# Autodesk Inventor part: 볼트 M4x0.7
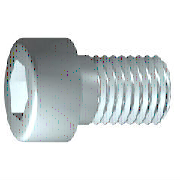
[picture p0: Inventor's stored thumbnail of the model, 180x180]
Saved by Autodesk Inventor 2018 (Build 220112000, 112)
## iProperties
IsCustomPart: 0
Created: 2012-02
Part Number: 볼트 M4x0.7
Material: 스테인리스강
Description: 6각 소켓 머리 캡 나사
Document SubType Name: Modeling
Standard: ISO 4762
Designer: mduedu
Standard Revision: Fourth edition 2004-03-01
Standards Organization: ISO
Language: ko-KR
Size Designation: M4 x 12
Categories: <MemberInstance><Categories><Category DisplayName="조임쇠" InternalName="e4da775c-781d-43d5-af7c-5136215cf5a6" Mnemonic="FSTN"><Category DisplayName="볼트" InternalN
Density: 7.75 g/cm^3
Appearance: 반광택
Author: mduedu
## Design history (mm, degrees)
sketch "스케치1"
  geometry: L1 (-1, 0)-(12, 0); L2 (12, 0)-(12, 2); L3 (12, 2)-(1.75, 2); L4 (1.75, 2)-(1.32, 2); L5 (1.32, 2)-(0, 2); L6 (0, 2)-(0, 3.5); L7 (0, 3.5)-(-4, 3.5); L8 (-4, 3.5)-(-4, 1.732); L9 (-4, 1.732)-(-2, 1.732); L10 (-2, 1.732)-(-1, 0); L11 (-7.2, 0)-(15.2, 0) reference; L12 (0, -0.7)-(0, 4.2) reference; L13 (1.75, 2)-(0, 2)
  constraints: 22 end point, 6 parallel, 2 collinear, 2 perpendicular, 1 horizontal, 1 point on line
  dimensions: "d1" = 10.25 distance from line of L3.end L2 (= GEL); "d2" = 0.42952 distance of L4.end L3.end (computed from GAL); "d3" = 4 distance between parallel lines of L8 L6 (= KOH); "d4" = 2 distance of L8.end L9.end (= INTI); "d5" = 60 deg angle of L10 L1; "d6" = 4 diameter of L3 L1 (= GD); "d7" = 4 diameter of L5 L1 (= BDM); "d8" = 3.4641 diameter of L9 L1 (= 1.1547 x SW); "d9" = 7 diameter of L7 L1 (= KOD); "d26" = 12 distance between parallel lines of L12 L2 (= NLG)
revolve "본체" sketch "스케치1" stored, may be unused: angle "d10" = 90 deg
sketch "스케치2"
  geometry: L1 (0, -4.9)-(0, 4.9) reference; L2 (-4.9, 0)-(4.9, 0) reference; L3 (1.732, 0)-(0.866, -1.5); L4 (0.866, -1.5)-(-0.866, -1.5); L5 (-0.866, -1.5)-(-1.732, 0); L6 (-1.732, 0)-(-0.866, 1.5); L7 (-0.866, 1.5)-(0.866, 1.5); L8 (0.866, 1.5)-(1.732, 0); 2 further points
  constraints: 12 end point, 1 coincident, 1 horizontal alignment, 1 point on line, 12 other
extrude "슬롯" join sketch "스케치2" stored distance "d11" = 10; taper "d12" = 0 deg
workplane "Work Plane1"
fillet "Fillet2" dims "d30" = 0.1 (= R)
body "Solid1"
fillet "모깎기1" dims "d17" = 0.4 (= RR)
feature "스레드" dims "d13" = 10.25 (= GEL), "d14" = 0
chamfer "모따기1" distance "d15" = 0.42941 (= -0.5 x SPD + 0.5 x GD); stored, may be unused: second distance "d16" = 0.42941 (= GUL), angle "d27" = 45 deg
other parameters: "GD" = 4 [user parameter; used in 2 equation terms], "NLG" = 12 [user parameter; used in 1 equation term], "GEL" = 10.25 [user parameter; used in 2 equation terms], "KOD" = 7 [user parameter; used in 1 equation term], "KOH" = 4 [user parameter; used in 1 equation term], "INTI" = 2 [user parameter; used in 1 equation term], "GAL" = 0.42941 (= 0.61345 x PTC) [user parameter; used in 1 equation term], "GUL" = 0.42941 (= 0.61345 x PTC) [user parameter; used in 1 equation term], "BDM" = 4 (= NND) [user parameter; used in 1 equation term], "SW" = 3 [user parameter; used in 2 equation terms], "RR" = 0.4 [user parameter; used in 1 equation term], "SPD" = 3.14117 (= NND - 1.2269 x PTC) [user parameter; used in 1 equation term], "d19" = 0, "d28" = 0, "d29" = 0, "R" = 0.1 [user parameter; used in 1 equation term], "TOA" = 30 deg [user parameter], "GD1" = 3.14117 (= THREADDIA - 1.2269 x PTC) [user parameter], "THREADDIA" = 4 [user parameter; used in 1 equation term], "FAWI" = 45 deg [user parameter], "TPU" = 14.28571 (computed from PTC) [user parameter], "PTC" = 0.7 [user parameter; used in 5 equation terms], "NND" = 4 [user parameter; used in 2 equation terms], "E0" = 3.465 (= 1.155 x SW) [user parameter]
